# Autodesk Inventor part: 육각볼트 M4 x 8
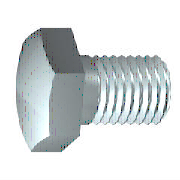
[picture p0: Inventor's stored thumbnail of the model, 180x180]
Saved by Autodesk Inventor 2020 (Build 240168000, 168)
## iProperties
Created: 2012-02
Part Number: 육각볼트 M4 x 8
Material: 강철, 연강
Description: 6각 머리 나사
Document SubType Name: Modeling
Standard: ISO 4017
Designer: mduedu
Standard Revision: Third edition 1999-08-15
Standards Organization: ISO
Language: ko-KR
Size Designation: M4 x 10
Categories: <MemberInstance><Categories><Category DisplayName="조임쇠" InternalName="e4da775c-781d-43d5-af7c-5136215cf5a6" Mnemonic="FSTN"><Category DisplayName="볼트" InternalN
Density: 7.86 g/cm^3
Appearance: 반광택
IsCustomPart: 0
Author: mduedu
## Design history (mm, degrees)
sketch "스케치1"
  geometry: L1 (0, 3.015)-(0, 2); L2 (1.75, 2)-(8, 2); L3 (8, 2)-(8, 0); L4 (8, 0)-(-0.4, 0); L5 (-2.08, 0)-(9.68, 0) reference; L6 (-0.4, 0)-(-0.4, 3.015); L7 (-0.4, 3.015)-(0, 3.015); L8 (1.75, 2)-(1.32, 2); L9 (1.32, 2)-(0, 2); L10 (0, -0.603)-(0, 3.618) reference
  constraints: 16 end point, 2 collinear, 2 perpendicular, 1 parallel
  dimensions: "d0" = 8 distance between parallel lines of L3 L1 (= NLG); "d1" = 6.25 distance from line of L2.start L3 (= GEL); "d2" = 4 diameter of L2 L4 (= GD); "d9" = 0.4001 distance between parallel lines of L6 L1 (computed from SD); "d10" = 6.03 diameter of L7 L4 (= SD2); "d13" = 0.42952 distance of L2.start L8.end (computed from GAL); "d14" = 4 diameter of L9 L4 (= BDM)
revolve "본체" sketch "스케치1" stored, may be unused: angle "d12" = 90 deg
sketch "스케치2"
  geometry: L1 (0, 4.041)-(3.5, 2.021); L2 (3.5, 2.021)-(3.5, -2.021); L3 (3.5, -2.021)-(0, -4.041); L4 (0, -4.041)-(-3.5, -2.021); L5 (-3.5, -2.021)-(-3.5, 2.021); L6 (-3.5, 2.021)-(0, 4.041); 2 further points
  constraints: 12 end point, 1 coincident, 1 vertical, 11 other
  dimensions: "d11" = 7 distance between parallel lines of L5 L2 (= SW)
extrude "머리" join sketch "스케치2" distance "d3" = 2.4 (= KOH - SD); taper "d4" = 0 deg
sketch "스케치4"
  geometry: L1 (-2.8, 3.5)-(-2.8, 4.041); L2 (-2.8, 4.041)-(-2.487, 4.041); L3 (-2.487, 4.041)-(-2.8, 3.5); L4 (-3.28, 0)-(0.08, 0) reference; L5 (-0.4, 4.041)-(-2.8, 4.041) reference; L6 (-2.8, 2.021)-(-2.8, 4.041) reference
  constraints: 6 end point, 2 collinear, 1 perpendicular, 1 vertical
  dimensions: "d5" = 30 deg angle of L3 L1 (= ANG1); "d19" = 7 diameter of L1.start L4 (= SW0)
revolve "모따기1" sketch "스케치4" stored, may be unused: angle "d21" = 90 deg
workplane "Work Plane1"
body "Solid1"
feature "스레드" dims "d15" = 6.25 (= GEL), "d16" = 0
chamfer "모따기2" distance "d6" = 0.42941 (= -0.5 x SPD + 0.5 x GD); stored, may be unused: second distance "d7" = 0.42952 (computed from GUL), angle "d55" = 45 deg
other parameters: "NLG" = 8 [user parameter; used in 1 equation term], "GD" = 4 (= NND) [user parameter; used in 2 equation terms], "BDM" = 4 (= NND) [user parameter; used in 1 equation term], "KOH" = 2.8 [user parameter; used in 1 equation term], "GEL" = 6.25 [user parameter; used in 2 equation terms], "SW" = 7 [user parameter; used in 2 equation terms], "SW0" = 7 (= SW) [user parameter; used in 1 equation term], "SPD" = 3.14117 (= NND - 1.2269 x PTC) [user parameter; used in 1 equation term], "SD2" = 6.03 [user parameter; used in 2 equation terms], "SD" = 0.4 [user parameter; used in 2 equation terms], "ANG1" = 30 deg [user parameter; used in 1 equation term], "GAL" = 0.42941 (= 0.61345 x PTC) [user parameter; used in 1 equation term], "GUL" = 0.42941 (= 0.61345 x PTC) [user parameter; used in 1 equation term], "d8" = 0, "RR" = 0.2 [user parameter], "d57" = 0, "d58" = 0, "TPU" = 14.28571 (computed from PTC) [user parameter], "GD1" = 3.14117 (= THREADDIA - 1.2269 x PTC) [user parameter], "THREADDIA" = 4 [user parameter; used in 1 equation term], "SDH" = 6.03 (= SD2) [user parameter], "SDHG" = 2.1 [user parameter], "TOA" = 30 deg [user parameter], "PTC" = 0.7 [user parameter; used in 5 equation terms], "NND" = 4 [user parameter; used in 3 equation terms], "E0" = 8.085 [user parameter]
